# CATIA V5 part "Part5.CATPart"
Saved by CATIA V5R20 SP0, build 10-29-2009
Part number: 9FP1406M5
Revision: ANY
Definition: UNKNOWN
Nomenclature: 9FP1406M5
Source: Unknown
Bounding box of the stored display mesh (mm): x -6.727 to 6.727, y 0 to 6, z -6.9 to 6.9
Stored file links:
  C:\Users\Utente\Desktop\IO LAVORO\3D X SITO CF\CUMSA\3D files PW\pw080825\pw080825_injection\Part5.CATPart
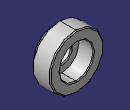
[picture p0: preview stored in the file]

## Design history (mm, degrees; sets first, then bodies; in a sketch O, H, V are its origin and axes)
Body1 "Chaflán1" (main body)
  Solid1: solid without history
